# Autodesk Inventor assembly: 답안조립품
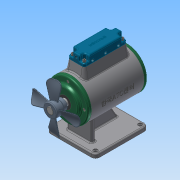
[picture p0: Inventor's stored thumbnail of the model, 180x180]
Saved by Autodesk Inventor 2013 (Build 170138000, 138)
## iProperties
Created: 2019-07
Part Number: 답안조립품
Document SubType Name: Assembly
Designer: Administrator
Author: Administrator
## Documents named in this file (19)
- C:\Users\Administrator\Desktop\390704V1071\답안조립품.iam
- C:\Users\Administrator\Desktop\390704V1071\본체.ipt
- C:\Users\Administrator\Desktop\390704V1071\가변스프링.ipt
- C:\Users\Administrator\Desktop\390704V1071\가변스프링2.ipt
- C:\Users\Administrator\Desktop\390704V1071\가변스프링3.ipt
- C:\Users\Administrator\Desktop\390704V1071\뒤커버.ipt
- C:\Users\Administrator\Desktop\390704V1071\멈춤나사 M4 x 5.ipt
- C:\Users\Administrator\Desktop\390704V1071\베어링 6203.ipt
- C:\Users\Administrator\Desktop\390704V1071\볼트 M4 x 12.ipt
- C:\Users\Administrator\Desktop\390704V1071\볼트 M4 x 16.ipt
- C:\Users\Administrator\Desktop\390704V1071\부시.ipt
- C:\Users\Administrator\Desktop\390704V1071\슬라이드.ipt
- C:\Users\Administrator\Desktop\390704V1071\앞커버.ipt
- C:\Users\Administrator\Desktop\390704V1071\오일실 17 30 8.ipt
- C:\Users\Administrator\Desktop\390704V1071\축.ipt
- C:\Users\Administrator\Desktop\390704V1071\키 5 x 5 x 18.ipt
- C:\Users\Administrator\Desktop\390704V1071\팬날개.ipt
- 팬날개.ipt
- C:\Users\Administrator\Desktop\390704V1071\헤더커버.ipt
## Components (4 placed, 4 different names)
1. 가변스프링:1
2. 가변스프링2:1
3. 가변스프링3:1
4. 헤더커버:1
